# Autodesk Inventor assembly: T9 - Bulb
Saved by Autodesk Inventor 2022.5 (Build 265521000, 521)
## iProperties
Created: 2024-07
Part Number: T9 - Bulb
Document SubType Name: Assembly
Designer: AdminForWorker
Title: T9 - Bulb v3
Author: AdminForWorker
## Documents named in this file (2)
- z:\worker\convert-fusion-r03-cosv3\tmp\job-1\79\temp\files\3a003a07-c448-400c-9cf1-292e8316b43e\T9 - Bulb v3.iam
- z:\worker\convert-fusion-r03-cosv3\tmp\job-1\79\temp\files\3a003a07-c448-400c-9cf1-292e8316b43e\T9 - LED Bulb.iam
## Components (1 placed, 1 different names)
1. T9 - LED Bulb:1 [sub-assembly]
